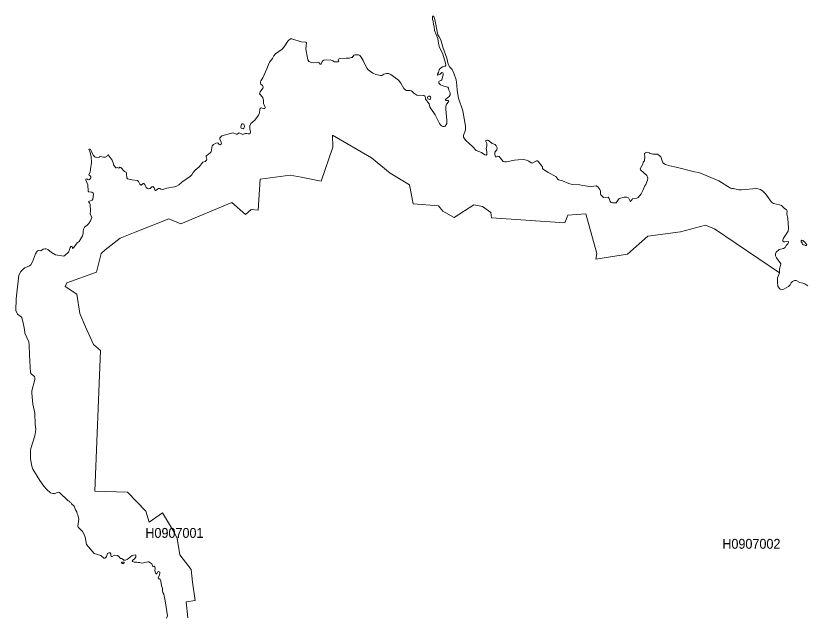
# Model space of a CAD drawing. Extents: x 369010 to 739155, y 6377141 to 6616555.
# Drawn here: x 449254 to 457235, y 6540160 to 6546215 of the extents above; entities that cross this region are included whole.
import ezdxf
from ezdxf.enums import TextEntityAlignment as Align

# ---------------------------------------------------------------- set-up
doc = ezdxf.new("R2010")
doc.units = 0
doc.header["$LTSCALE"] = 40
doc.layers.add('1', color=7, linetype='Continuous', lineweight=13)
doc.layers.add('2', color=7, linetype='Continuous')

msp = doc.modelspace()

# ---------------------------------------------------------------- linework, layer by layer
at = {"layer": '1'}
for points in [[(454547.31, 6544711.14), (454526.62, 6544743.74), (454515.7, 6544751.85), (454504.61, 6544753.51), (454461.24, 6544729.51), (454449.99, 6544731.66), (454426.65, 6544748.38), (454403.98, 6544758.8), (454375.84, 6544764.26), (454320.9, 6544763.93), (454284.98, 6544759.8), (454201.73, 6544741.09), (454186.18, 6544741.76), (454169.79, 6544746.89), (454127.59, 6544794.88), (454114.02, 6544799.68), (454101.6, 6544792.73), (454093.16, 6544793.23), (454088.69, 6544799.68), (454084.23, 6544824.01), (454086.54, 6544839.07), (454105.08, 6544864.06), (454109.55, 6544882.1), (454099.78, 6544905.11), (454088.2, 6544916.2), (454058.57, 6544927.29), (454029.78, 6544952.28), (454014.55, 6544961.05), (454003.13, 6544962.04), (453995.35, 6544956.41), (453994.36, 6544946.81), (454004.45, 6544928.61), (454004.29, 6544900.8), (453996.34, 6544875.48), (454004.29, 6544841.89), (454005.94, 6544823.68), (454002.8, 6544815.74), (453996.01, 6544810.6), (453984.43, 6544811.93), (453949.34, 6544835.93), (453895.72, 6544855.29), (453859.47, 6544898.49), (453824.72, 6544925.96), (453788.14, 6544960.72), (453769.44, 6544990.51), (453768.28, 6545009.38), (453789.63, 6545064.82), (453789.3, 6545103.05), (453762.82, 6545257.47), (453720.12, 6545384.9), (453704.73, 6545460.04), (453701.91, 6545514.66), (453693.47, 6545568.78), (453670.47, 6545637.63), (453653.58, 6545672.38), (453632.73, 6545697.71), (453614.19, 6545728.32), (453600.62, 6545789.23), (453559.91, 6545897.64), (453539.55, 6545971.62), (453524.49, 6546003.89), (453511.42, 6546022.76), (453479.64, 6546178.83), (453469.88, 6546206.96), (453460.11, 6546214.91), (453455.97, 6546208.95), (453456.97, 6546178.83), (453463.59, 6546159.96), (453466.07, 6546128.35), (453473.35, 6546106.17), (453477.65, 6546067.94), (453509.43, 6545987.17), (453515.72, 6545938.51), (453520.85, 6545927.09), (453524.82, 6545904.26), (453560.41, 6545828.79), (453587.55, 6545738.09), (453590.69, 6545717.24), (453585.07, 6545706.48), (453570.01, 6545705.32), (453556.93, 6545700.19), (453534.26, 6545683.8), (453522.17, 6545669.57), (453516.22, 6545644.25), (453506.45, 6545626.54), (453507.94, 6545619.26), (453511.42, 6545616.77), (453534.59, 6545627.86), (453551.3, 6545642.92), (453559.25, 6545640.11), (453564.21, 6545632), (453565.21, 6545618.1), (453551.97, 6545570.27), (453540.21, 6545561.83), (453523.83, 6545556.37), (453518.7, 6545547.59), (453521.02, 6545536.51), (453535.91, 6545519.79), (453570.67, 6545503.9), (453611.55, 6545494.14)], [(453484.94, 6545215.76), (453439.42, 6545279.97), (453429.66, 6545297.35), (453422.54, 6545327.31), (453386.46, 6545374.15), (453386.13, 6545392.35), (453378.35, 6545403.77), (453369.08, 6545410.72), (453300.07, 6545413.2), (453267.79, 6545435.71), (453243.63, 6545458.72), (453231.05, 6545462.19), (453190.84, 6545461.86), (453168.16, 6545480.9), (453138.04, 6545536.17), (453113.88, 6545565.3), (453035.1, 6545624.39), (453011.43, 6545633.49), (452993.72, 6545633.49), (452965.09, 6545626.21), (452947.05, 6545614.62), (452930.99, 6545614.62), (452886.14, 6545622.4), (452854.86, 6545635.15), (452807.53, 6545671.06), (452797.43, 6545682.81), (452780.72, 6545712.44), (452758.54, 6545762.75), (452737.19, 6545799.33), (452724.28, 6545813.56), (452709.72, 6545820.18), (452693.66, 6545822.83), (452672.15, 6545822.5), (452663.21, 6545817.03), (452645.5, 6545794.69), (452634.91, 6545794.69), (452619.18, 6545787.74), (452586.25, 6545787.74), (452514.09, 6545780.79), (452507.47, 6545776.98), (452506.48, 6545771.02), (452511.61, 6545755.8), (452506.15, 6545750.34), (452468.74, 6545749.51), (452451.03, 6545761.43), (452428.03, 6545771.19), (452359.01, 6545767.22), (452350.74, 6545762.42), (452340.64, 6545747.19), (452335.18, 6545731.47), (452328.89, 6545725.68), (452323.93, 6545726.67), (452312.51, 6545741.9), (452300.76, 6545747.52), (452255.08, 6545741.23), (452234.88, 6545744.05), (452210.22, 6545753.48), (452200.46, 6545769.37), (452195.33, 6545788.57), (452179.77, 6545881.91), (452184.57, 6545941.33), (452180.1, 6545948.78), (452130.29, 6545953.91), (452037.77, 6545984.19), (452023.54, 6545981.38), (452007.48, 6545970.95), (451995.9, 6545958.38), (451961.97, 6545901.44), (451941.61, 6545878.77), (451873.09, 6545832.26), (451855.38, 6545812.07), (451841.32, 6545784.6), (451812.19, 6545748.19), (451787.2, 6545681.82), (451745.32, 6545590.79), (451725.13, 6545559.18), (451720.17, 6545545.61), (451721.66, 6545534.85), (451726.79, 6545525.42), (451742.84, 6545510.85), (451748.14, 6545496.95), (451746.15, 6545485.36), (451717.85, 6545447.96), (451713.22, 6545428.43), (451745.32, 6545391.52), (451752.27, 6545362.06), (451750.62, 6545338.07), (451753.1, 6545328.3), (451767, 6545304.8), (451768.33, 6545290.07), (451766.34, 6545281.79), (451758.56, 6545277.99), (451729.1, 6545286.26), (451719.34, 6545279.31), (451714.54, 6545268.89), (451711.89, 6545235.95), (451701.47, 6545211.62), (451664.23, 6545161.97), (451624.84, 6545127.21), (451614.08, 6545105.86)], [(453611.55, 6545494.14), (453618.83, 6545483.71), (453621.31, 6545465.17), (453634.55, 6545436.71), (453633.23, 6545418.34), (453623.96, 6545402.28), (453591.69, 6545374.15), (453585.73, 6545364.55), (453589.87, 6545360.24), (453616.18, 6545361.07), (453619.99, 6545354.12), (453618.17, 6545346.01), (453595.99, 6545323.83), (453590.03, 6545301.99), (453589.37, 6545274.84), (453602.11, 6545161.47), (453601.62, 6545128.87), (453584.57, 6545102.39), (453574.14, 6545097.59), (453560.9, 6545098.91), (453547, 6545104.54), (453536.9, 6545113.97), (453526.81, 6545127.88), (453484.94, 6545215.76)], [(451614.08, 6545105.86), (451613.42, 6545076.4), (451620.04, 6545044.46), (451618.22, 6545029.07), (451612.42, 6545024.6), (451596.37, 6545024.93), (451583.46, 6545029.57), (451566.41, 6545029.07), (451544.57, 6545016.66), (451530.5, 6545025.59), (451507.99, 6545033.04), (451485.65, 6545022.62), (451477.7, 6545022.62), (451447.75, 6545033.37), (451430.54, 6545032.55), (451330.24, 6545005.24), (451311.7, 6544983.23), (451311.04, 6544971.14), (451324.78, 6544939.53), (451327.26, 6544926.62), (451324.12, 6544921), (451315.34, 6544915.2), (451303.59, 6544917.52), (451293.17, 6544929.77), (451284.56, 6544934.24), (451272.31, 6544931.42), (451246.99, 6544918.35), (451234.41, 6544902.96), (451223.16, 6544844.2), (451214.55, 6544832.78), (451178.97, 6544805.64), (451173.18, 6544798.03), (451172.35, 6544789.75), (451178.47, 6544781.31), (451181.62, 6544769.23), (451176.82, 6544757.64), (451163.58, 6544746.22), (451139.91, 6544737.62), (451101.68, 6544690.28), (451063.12, 6544659.33), (451041.6, 6544635.67), (451028.19, 6544609.68), (451016.78, 6544597.1), (450929.06, 6544536.36), (450896.78, 6544508.89), (450875.77, 6544497.47), (450852.76, 6544489.69), (450777.13, 6544476.62), (450735.42, 6544462.72), (450718.04, 6544465.03), (450705.63, 6544471.65), (450693.38, 6544471.98), (450670.04, 6544455.43), (450661.6, 6544454.61), (450654.65, 6544459.57), (450648.03, 6544481.09), (450636.28, 6544491.84), (450625.85, 6544489.36), (450609.14, 6544472.81), (450595.57, 6544468.84), (450582.49, 6544473.14), (450568.42, 6544484.89), (450555.52, 6544513.03), (450546.08, 6544522.13), (450537.48, 6544522.46), (450519.27, 6544508.23), (450511.99, 6544508.56), (450504.71, 6544516.5), (450492.62, 6544543.98), (450481.54, 6544553.41), (450424.6, 6544560.03), (450379.09, 6544571.12), (450372.47, 6544581.22), (450371.14, 6544620.11), (450366.51, 6544638.15), (450349.79, 6544644.77), (450314.05, 6544683.99), (450304.11, 6544688.63), (450293.03, 6544677.71), (450277.63, 6544683.99), (450269.03, 6544680.19), (450261.41, 6544682.34), (450238.41, 6544712.46), (450239.73, 6544721.89), (450226.33, 6544759.8), (450185.78, 6544811.6), (450178.83, 6544808.78), (450170.55, 6544795.88), (450158.64, 6544788.92), (450138.11, 6544789.42), (450105.01, 6544795.54), (450095.25, 6544790.41), (450063.31, 6544786.28), (450052.22, 6544791.41), (450038.65, 6544805.97), (450002.9, 6544868.86), (449992.8, 6544870.02), (449990.98, 6544865.06), (450000.75, 6544846.02), (450014.65, 6544796.7)], [(450988.97, 6540143.56), (450973.25, 6540302.94), (451062.12, 6540318.66), (451035.97, 6540501.71), (451022.9, 6540629.64), (450908.37, 6540777.11), (450879.74, 6540941.78), (450853.59, 6540999.38), (450733.27, 6541203.28), (450600.04, 6541106.46), (450565.94, 6541218.84), (450381.41, 6541411.32), (450052.05, 6541419.1), (450109.65, 6542839.62), (450037.49, 6542898.37), (449956.56, 6543078.77), (449898.96, 6543212), (449870.16, 6543407.96), (449752.66, 6543486.41), (449768.21, 6543522.98), (450066.29, 6543630.23), (450114.12, 6543817.08), (450155.99, 6543856.14), (450307.59, 6543971.17), (450459.19, 6544033.89), (450796.32, 6544167.29), (450916.65, 6544117.64), (451432.69, 6544330.97), (451571.21, 6544210.82), (451626.16, 6544260.47), (451699.31, 6544255.17), (451717.68, 6544566.32), (452020.89, 6544608.03), (452133.27, 6544587.17), (452335.18, 6544547.29), (452450.21, 6544889.72), (452447.56, 6545012.52), (452842.28, 6544782.47), (453029.63, 6544629.05), (453222.94, 6544511.54), (453262.17, 6544318.07), (453515.72, 6544297.21), (453560.24, 6544244.91), (453675.27, 6544182.19), (453873.21, 6544308.63), (453959.44, 6544292.91), (454043.18, 6544230.18), (454050.96, 6544178.05), (454791.26, 6544128.23), (454822.54, 6544204.03), (455002.94, 6544217.11), (455112.67, 6543817.08), (455104.89, 6543759.65), (455421.66, 6543811.79), (455628.21, 6543992.19), (455957.4, 6544036.71), (456210.95, 6544104.56), (456299.83, 6544065.34), (456956.88, 6543623.44), (456956.88, 6543664.16), (456967.47, 6543697.26), (456967.97, 6543711.82), (456924.44, 6543773.72), (456917.32, 6543792.76), (456916, 6543813.44), (456923.61, 6543832.48), (456954.07, 6543858.96), (456997.43, 6543867.07), (457013.32, 6543878.98)], [(457242.37, 6543491.87), (457211.26, 6543512.56), (457192.23, 6543519.18), (457161.28, 6543523.65), (457124.2, 6543544), (457108.32, 6543544.83), (457087.96, 6543535.07), (457074.72, 6543522.32), (457064.13, 6543500.64), (457045.26, 6543484.75), (456998.09, 6543459.1), (456978.56, 6543452.15), (456963.17, 6543457.78), (456952.74, 6543467.54), (456940.83, 6543489.55), (456934.21, 6543528.11), (456936.36, 6543572.64), (456956.88, 6543623.44), (456299.83, 6544065.34), (456210.95, 6544104.56), (455957.4, 6544036.71), (455628.21, 6543992.19), (455421.66, 6543811.79), (455104.89, 6543759.65), (455112.67, 6543817.08), (455002.94, 6544217.11), (454822.54, 6544204.03), (454791.26, 6544128.23), (454050.96, 6544178.05), (454043.18, 6544230.18), (453959.44, 6544292.91), (453873.21, 6544308.63), (453675.27, 6544182.19), (453560.24, 6544244.91), (453515.72, 6544297.21), (453262.17, 6544318.07), (453222.94, 6544511.54), (453029.63, 6544629.05), (452842.28, 6544782.47), (452447.56, 6545012.52), (452450.21, 6544889.72), (452335.18, 6544547.29), (452133.27, 6544587.17), (452020.89, 6544608.03), (451717.68, 6544566.32), (451699.31, 6544255.17), (451626.16, 6544260.47), (451571.21, 6544210.82), (451432.69, 6544330.97), (450916.65, 6544117.64), (450796.32, 6544167.29), (450459.19, 6544033.89), (450307.59, 6543971.17), (450155.99, 6543856.14)], [(450014.65, 6544796.7), (450015.81, 6544734.47), (450007.86, 6544666.95), (450002.24, 6544637.49), (449991.64, 6544613.16), (449993.13, 6544605.21), (450002.4, 6544599.92), (450009.85, 6544590.15), (450009.85, 6544581.22), (450001.08, 6544568.97), (449989, 6544561.69), (449980.22, 6544562.35), (449969.13, 6544570.46), (449961.85, 6544567.65), (449960.36, 6544558.54), (449979.56, 6544511.37), (449982.71, 6544444.68), (449989.99, 6544439.05), (450020.94, 6544434.58), (450033.68, 6544427.63), (450037.16, 6544414.72), (450032.03, 6544366.72), (450022.59, 6544354.31), (449988.17, 6544341.07), (449989.33, 6544335.11), (449998.26, 6544327.17), (450004.22, 6544312.27), (450008.52, 6544246.9), (450002.73, 6544213.14), (450018.95, 6544192.28), (450020.77, 6544179.87), (450007.37, 6544145.78), (449991.64, 6544119.63), (449967.48, 6544095.96), (449957.55, 6544092.15), (449946.3, 6544082.06), (449935.21, 6544062.36), (449931.73, 6544043.82), (449932.89, 6544018.83), (449925.44, 6543997.32), (449891.35, 6543938.9), (449873.97, 6543926.81), (449836.73, 6543873.69), (449827.3, 6543868.72), (449824.15, 6543882.95), (449816.87, 6543888.25), (449808.26, 6543887.92), (449800.65, 6543879.15), (449792.05, 6543847.54), (449783.77, 6543832.64), (449753.15, 6543799.54), (449738.59, 6543790.6), (449654.02, 6543805.5), (449614.46, 6543827.35), (449577.72, 6543858.96), (449560.34, 6543865.58), (449545.78, 6543865.25), (449530.05, 6543860.45), (449505.06, 6543845.39), (449479.74, 6543849.36), (449469.15, 6543841.91), (449453.42, 6543813.44), (449421.65, 6543734.99), (449404.27, 6543704.38), (449393.51, 6543691.8), (449345.52, 6543673.1), (449332.61, 6543662.34), (449303.64, 6543634.86), (449284.61, 6543599.12), (449255.98, 6543359.96), (449254.16, 6543243.94), (449269.55, 6543206.37), (449307.12, 6543179.56), (449313.08, 6543171.29), (449332.44, 6543101.45), (449342.37, 6543052.12), (449344.85, 6543015.55), (449384.57, 6542927), (449389.71, 6542897.05), (449392.52, 6542794.44), (449402.95, 6542614.2), (449411.55, 6542601.62), (449441.51, 6542577.62), (449446.14, 6542564.05), (449445.81, 6542546.34), (449416.85, 6542431.98), (449415.69, 6542410.13), (449424.3, 6542298.59), (449444.32, 6542206.23), (449449.29, 6542091.54), (449454.91, 6542046.03), (449453.09, 6542017.39), (449444.32, 6541978.17), (449404.1, 6541850.73), (449401.95, 6541831.53), (449403.77, 6541744.97), (449415.69, 6541672.65), (449424.63, 6541642.86), (449495.79, 6541526.34), (449535.35, 6541470.73)], [(457013.32, 6543878.98), (457023.91, 6543898.84), (457041.12, 6543915.56), (457046.42, 6543928.47), (457045.09, 6543937.24), (457009.67, 6543933.76), (456998.26, 6543935.42), (456991.14, 6543942.04), (456990.31, 6543953.63), (456997.76, 6543972.66), (457043.93, 6544043.33), (457048.4, 6544074.28), (457040.62, 6544169.61), (457028.71, 6544219.09), (457032.85, 6544246.07), (457028.05, 6544257.99), (457003.39, 6544276.19), (456977.24, 6544300.85), (456956.55, 6544308.47), (456895.48, 6544320.38), (456875.45, 6544336.27), (456817.52, 6544414.88), (456787.24, 6544446.33), (456764.23, 6544461.89), (456724.51, 6544474.8), (456574.07, 6544460.23), (456547.42, 6544460.89), (456491.81, 6544471.65), (456474.93, 6544471.65), (456461.36, 6544476.12), (456342.69, 6544549.44), (456142.93, 6544635.34), (456100.06, 6544640.63), (455914.53, 6544687.47), (455850.48, 6544700.71), (455805.96, 6544715.61), (455780.81, 6544731.33), (455758.63, 6544792.07), (455739.1, 6544810.11), (455725.53, 6544818.22), (455679.52, 6544818.22), (455650.72, 6544827.16), (455639.96, 6544834.11), (455619.11, 6544839.07), (455603.72, 6544834.11), (455595.11, 6544826.82), (455593.62, 6544816.4), (455597.1, 6544794.55), (455593.13, 6544753.51), (455582.7, 6544738.94), (455576.41, 6544719.41), (455550.1, 6544672.91), (455554.23, 6544660.33), (455618.28, 6544605.88), (455627.05, 6544578.73), (455625.56, 6544558.21), (455608.85, 6544514.02), (455598.09, 6544498.46), (455578.89, 6544452.62), (455560.03, 6544418.53), (455530.73, 6544382.78), (455515.5, 6544376.16), (455473.14, 6544370.2), (455454.43, 6544342.73), (455448.31, 6544345.87), (455433.25, 6544380.63), (455416.2, 6544387.25), (455390.55, 6544384.43), (455339.24, 6544371.52), (455320.54, 6544350.01), (455316.07, 6544337.1), (455307.96, 6544329.82), (455273.37, 6544327.17), (455258.97, 6544331.97), (455248.05, 6544342.73), (455238.78, 6544373.34), (455228.36, 6544384.43), (455181.68, 6544383.77), (455154.87, 6544409.75), (455150.24, 6544419.52), (455150.24, 6544445.34), (455144.44, 6544464.37), (455124.92, 6544489.69), (455106.21, 6544498.46), (455060.2, 6544494.33), (455020.48, 6544495.32), (454971.49, 6544502.6), (454942.86, 6544510.88), (454864.91, 6544514.35), (454831.48, 6544523.79), (454768.59, 6544551.59), (454727.71, 6544560.69), (454718.77, 6544568.31), (454699.57, 6544595.12), (454621.78, 6544635.34), (454610.03, 6544645.43), (454574.61, 6544663.8), (454567.33, 6544673.9), (454564.52, 6544692.44), (454547.31, 6544711.14)], [(450155.99, 6543856.14), (450114.12, 6543817.08), (450066.29, 6543630.23), (449768.21, 6543522.98), (449752.66, 6543486.41), (449870.16, 6543407.96), (449898.96, 6543212), (449956.56, 6543078.77), (450037.49, 6542898.37), (450109.65, 6542839.62), (450052.05, 6541419.1), (450381.41, 6541411.32), (450565.94, 6541218.84), (450600.04, 6541106.46), (450733.27, 6541203.28), (450853.59, 6540999.38), (450879.74, 6540941.78), (450908.37, 6540777.11), (451022.9, 6540629.64), (451035.97, 6540501.71), (451062.12, 6540318.66), (450973.25, 6540302.94), (450988.97, 6540143.56)], [(449535.35, 6541470.73), (449566.63, 6541435.98), (449602.21, 6541404.86), (449627.87, 6541396.42), (449643.09, 6541395.76), (449656.66, 6541399.24), (449680.33, 6541411.81), (449694.23, 6541405.86), (449781.78, 6541321.78), (449794.03, 6541320.29), (449799.49, 6541311.02), (449809.26, 6541305.4), (449815.22, 6541294.31), (449843.02, 6541269.98), (449856.26, 6541231.08), (449870.33, 6541211.89), (449871.98, 6541195.17), (449877.94, 6541183.09), (449889.03, 6541139.23), (449880.09, 6541067.4), (449883.57, 6541056.15), (449926.43, 6541013.78), (449940.34, 6540988.46), (449952.92, 6540957.18), (449968.14, 6540883.2), (450045.27, 6540790.02), (450111.14, 6540771.98), (450140.93, 6540745.5), (450152.35, 6540745.5), (450161.78, 6540750.46), (450169.73, 6540762.87), (450177.84, 6540792.17), (450191.24, 6540797.96), (450206.47, 6540797.96), (450212.76, 6540789.02), (450212.43, 6540767.84), (450217.23, 6540762.54), (450226.66, 6540761.88), (450249.5, 6540774.46), (450278.79, 6540770.98), (450293.85, 6540761.22), (450308.75, 6540739.7), (450322.32, 6540740.03), (450344.5, 6540725.3), (450360.72, 6540724.64), (450378.43, 6540730.27), (450427.75, 6540772.31), (450458.36, 6540778.93), (450465.32, 6540773.96), (450462.83, 6540753.94), (450455.22, 6540742.02), (450433.37, 6540724.97), (450428.41, 6540716.04), (450429.9, 6540711.07), (450446.45, 6540705.61), (450474.92, 6540705.61), (450487, 6540700.64), (450505.86, 6540700.31), (450520.43, 6540695.51), (450540.12, 6540697.17), (450586.96, 6540709.08), (450597.06, 6540707.6), (450624.53, 6540686.74), (450633.47, 6540666.72), (450640.75, 6540660.76), (450649.52, 6540663.57), (450656.47, 6540657.28), (450660.94, 6540641.23), (450656.64, 6540620.37), (450661.44, 6540596.05), (450668.39, 6540586.78), (450676.83, 6540585.62), (450685.77, 6540606.8), (450693.38, 6540610.78), (450704.97, 6540603.82), (450707.28, 6540590.58), (450703.81, 6540576.02), (450689.74, 6540544.74), (450693.55, 6540535.97), (450701.99, 6540535.31), (450708.61, 6540530.51), (450717.21, 6540512.8), (450723.5, 6540469.6), (450734.92, 6540439.31), (450734.59, 6540414.16), (450737.4, 6540399.76), (450746.67, 6540380.39), (450759.42, 6540315.19), (450782.59, 6540163.91), (450774.31, 6540138.43)]]:
    msp.add_lwpolyline(points, dxfattribs=at)
for points in [[(453428.33, 6545371.83), (453435.29, 6545377.29), (453439.09, 6545390.53), (453437.11, 6545399.3), (453430.49, 6545404.76), (453417.58, 6545405.1), (453408.64, 6545400.63), (453405.83, 6545390.2), (453410.29, 6545376.3)], [(451547.05, 6545074.58), (451554.33, 6545081.2), (451559.96, 6545095.11), (451558.14, 6545115.63), (451552.18, 6545122.58), (451543.91, 6545124.73), (451537.62, 6545124.07), (451530.67, 6545118.44), (451525.53, 6545108.68), (451522.39, 6545090.31), (451527.52, 6545080.87)], [(457227.97, 6543898.68), (457230.29, 6543905.63), (457211.59, 6543932.61), (457190.9, 6543949.82), (457182.13, 6543950.81), (457174.52, 6543944.19), (457175.01, 6543935.75), (457184.78, 6543925.66), (457187.43, 6543907.95), (457194.87, 6543903.48), (457204.64, 6543905.3), (457217.38, 6543899.01)], [(450341.85, 6540705.61), (450327.12, 6540705.28), (450318.84, 6540698.66), (450321.66, 6540691.71), (450338.71, 6540689.56), (450345.99, 6540694.52), (450347.97, 6540699.65)]]:
    msp.add_lwpolyline(points, close=True, dxfattribs=at)

# ---------------------------------------------------------------- texts
at = {"layer": '2', "width": 0.95}
for s, p in [('H0907001', (450853.58, 6540949.38)), ('H0907002', (456672.41, 6540839.3))]:
    msp.add_text(s, height=100, dxfattribs=at).set_placement(p, align=Align.CENTER)

doc.saveas('drawing.dxf')
